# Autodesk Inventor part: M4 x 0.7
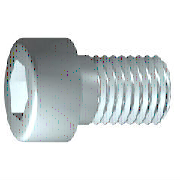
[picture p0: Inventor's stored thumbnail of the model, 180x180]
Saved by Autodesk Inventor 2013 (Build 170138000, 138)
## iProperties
IsCustomPart: 0
Created: 2015-10
Part Number: M4 x 0.7
Material: 강철, 연강
Description: 6각머리 태핑 나사
Document SubType Name: Modeling
Standard: KS B 1003
Designer: mdu
Standards Organization: KS
Language: ko-KR
Size Designation: M 4 x 25
Categories: <MemberInstance><Categories><Category DisplayName="조임쇠" InternalName="e4da775c-781d-43d5-af7c-5136215cf5a6" Mnemonic="FSTN"><Category DisplayName="볼트" InternalN
Density: 7.86 g/cm^3
Mass: 3.51868 g
Surface Area: 4.94215 cm^2
Volume: 0.447669 cm^3
Author: mdu
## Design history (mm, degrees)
sketch "스케치1"
  geometry: L1 (-1, 0)-(25, 0); L2 (25, 0)-(25, 2); L3 (25, 2)-(1.75, 2); L4 (1.75, 2)-(1.32, 2); L5 (1.32, 2)-(0, 2); L6 (0, 2)-(0, 3.5); L7 (0, 3.5)-(-4, 3.5); L8 (-4, 3.5)-(-4, 1.732); L9 (-4, 1.732)-(-2, 1.732); L10 (-2, 1.732)-(-1, 0); L11 (-9.8, 0)-(30.8, 0) reference; L12 (0, -0.7)-(0, 4.2) reference; L13 (1.75, 2)-(0, 2)
  constraints: 22 end point, 6 parallel, 2 collinear, 2 perpendicular, 1 horizontal, 1 point on line
  dimensions: "d1" = 23.25 distance from line of L3.end L2 (= GEL); "d2" = 0.42952 distance of L4.end L3.end (computed from GAL); "d3" = 4 distance between parallel lines of L8 L6 (= KOH); "d4" = 2 distance of L8.end L9.end (= INTI); "d5" = 60 deg angle of L10 L1; "d6" = 4 diameter of L3 L1 (= GD); "d7" = 4 diameter of L5 L1 (= BDM); "d8" = 3.4641 diameter of L9 L1 (= 1.1547 x SW); "d9" = 7 diameter of L7 L1 (= KOD); "d26" = 25 distance between parallel lines of L12 L2 (= NLG)
revolve "본체" sketch "스케치1" stored, may be unused: angle "d10" = 90 deg
sketch "스케치2"
  geometry: L1 (0, -4.9)-(0, 4.9) reference; L2 (-4.9, 0)-(4.9, 0) reference; L3 (1.732, 0)-(0.866, -1.5); L4 (0.866, -1.5)-(-0.866, -1.5); L5 (-0.866, -1.5)-(-1.732, 0); L6 (-1.732, 0)-(-0.866, 1.5); L7 (-0.866, 1.5)-(0.866, 1.5); L8 (0.866, 1.5)-(1.732, 0); 2 further points
  constraints: 12 end point, 1 coincident, 1 horizontal alignment, 1 point on line, 12 other
extrude "슬롯" join sketch "스케치2" stored distance "d11" = 10; taper "d12" = 0 deg
workplane "Work Plane1"
fillet "Fillet2" dims "d30" = 0.1 (= R)
body "Solid1"
fillet "모깎기1" dims "d17" = 0.4 (= RR)
feature "스레드" dims "d13" = 23.25 (= GEL), "d14" = 0
chamfer "모따기1" distance "d15" = 0.42941 (= -0.5 x SPD + 0.5 x GD); stored, may be unused: second distance "d16" = 0.42941 (= GUL), angle "d27" = 45 deg
other parameters: "GD" = 4 (= NND) [user parameter; used in 2 equation terms], "NLG" = 25 [user parameter; used in 1 equation term], "GEL" = 23.25 [user parameter; used in 2 equation terms], "KOD" = 7 [user parameter; used in 1 equation term], "KOH" = 4 [user parameter; used in 1 equation term], "INTI" = 2 [user parameter; used in 1 equation term], "GAL" = 0.42941 (= 0.61345 x PTC) [user parameter; used in 1 equation term], "GUL" = 0.42941 (= 0.61345 x PTC) [user parameter; used in 1 equation term], "BDM" = 4 (= NND) [user parameter; used in 1 equation term], "SW" = 3 [user parameter; used in 2 equation terms], "RR" = 0.4 [user parameter; used in 1 equation term], "SPD" = 3.14117 (= NND - 1.2269 x PTC) [user parameter; used in 1 equation term], "d19" = 0, "d28" = 0, "d29" = 0, "R" = 0.1 [user parameter; used in 1 equation term], "PHH" = 0.2 [user parameter], "GD1" = 3.14117 (= THREADDIA - 1.2269 x PTC) [user parameter], "THREADDIA" = 4 [user parameter; used in 1 equation term], "FAWI" = 45 deg [user parameter], "TPU" = 14.28571 (computed from PTC) [user parameter], "PTC" = 0.7 [user parameter; used in 5 equation terms], "NND" = 4 [user parameter; used in 3 equation terms], "TOA" = 30 deg [user parameter], "E0" = 3.465 (= 1.155 x SW) [user parameter]
